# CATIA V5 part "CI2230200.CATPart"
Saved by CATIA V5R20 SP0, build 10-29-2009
Part number: 2230200_ASM
Bounding box of the stored display mesh (mm): x -29 to 29, y -23.836 to 245, z -41.554 to 32.071
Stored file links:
  C:\Users\Raffaele\Desktop\3D X SITO CF\BOLEX\19-INCLINED ASSEMBLY REF_CI\CI2230200.CATPart

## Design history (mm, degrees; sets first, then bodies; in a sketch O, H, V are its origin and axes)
Set1
  DatumSurface1 to DatumSurface16 "MANIFOLD_SOLID_BREP #397"
  DatumSurface17 to DatumSurface39 "MANIFOLD_SOLID_BREP #1171"
Body1 (main body)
